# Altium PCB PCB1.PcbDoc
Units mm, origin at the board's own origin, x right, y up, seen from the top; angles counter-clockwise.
Board outline 66.23 x 50.49 mm, 2 copper layers (Top Layer, Bottom Layer); 33 components, 24 nets, 102 pads, 82 vias.
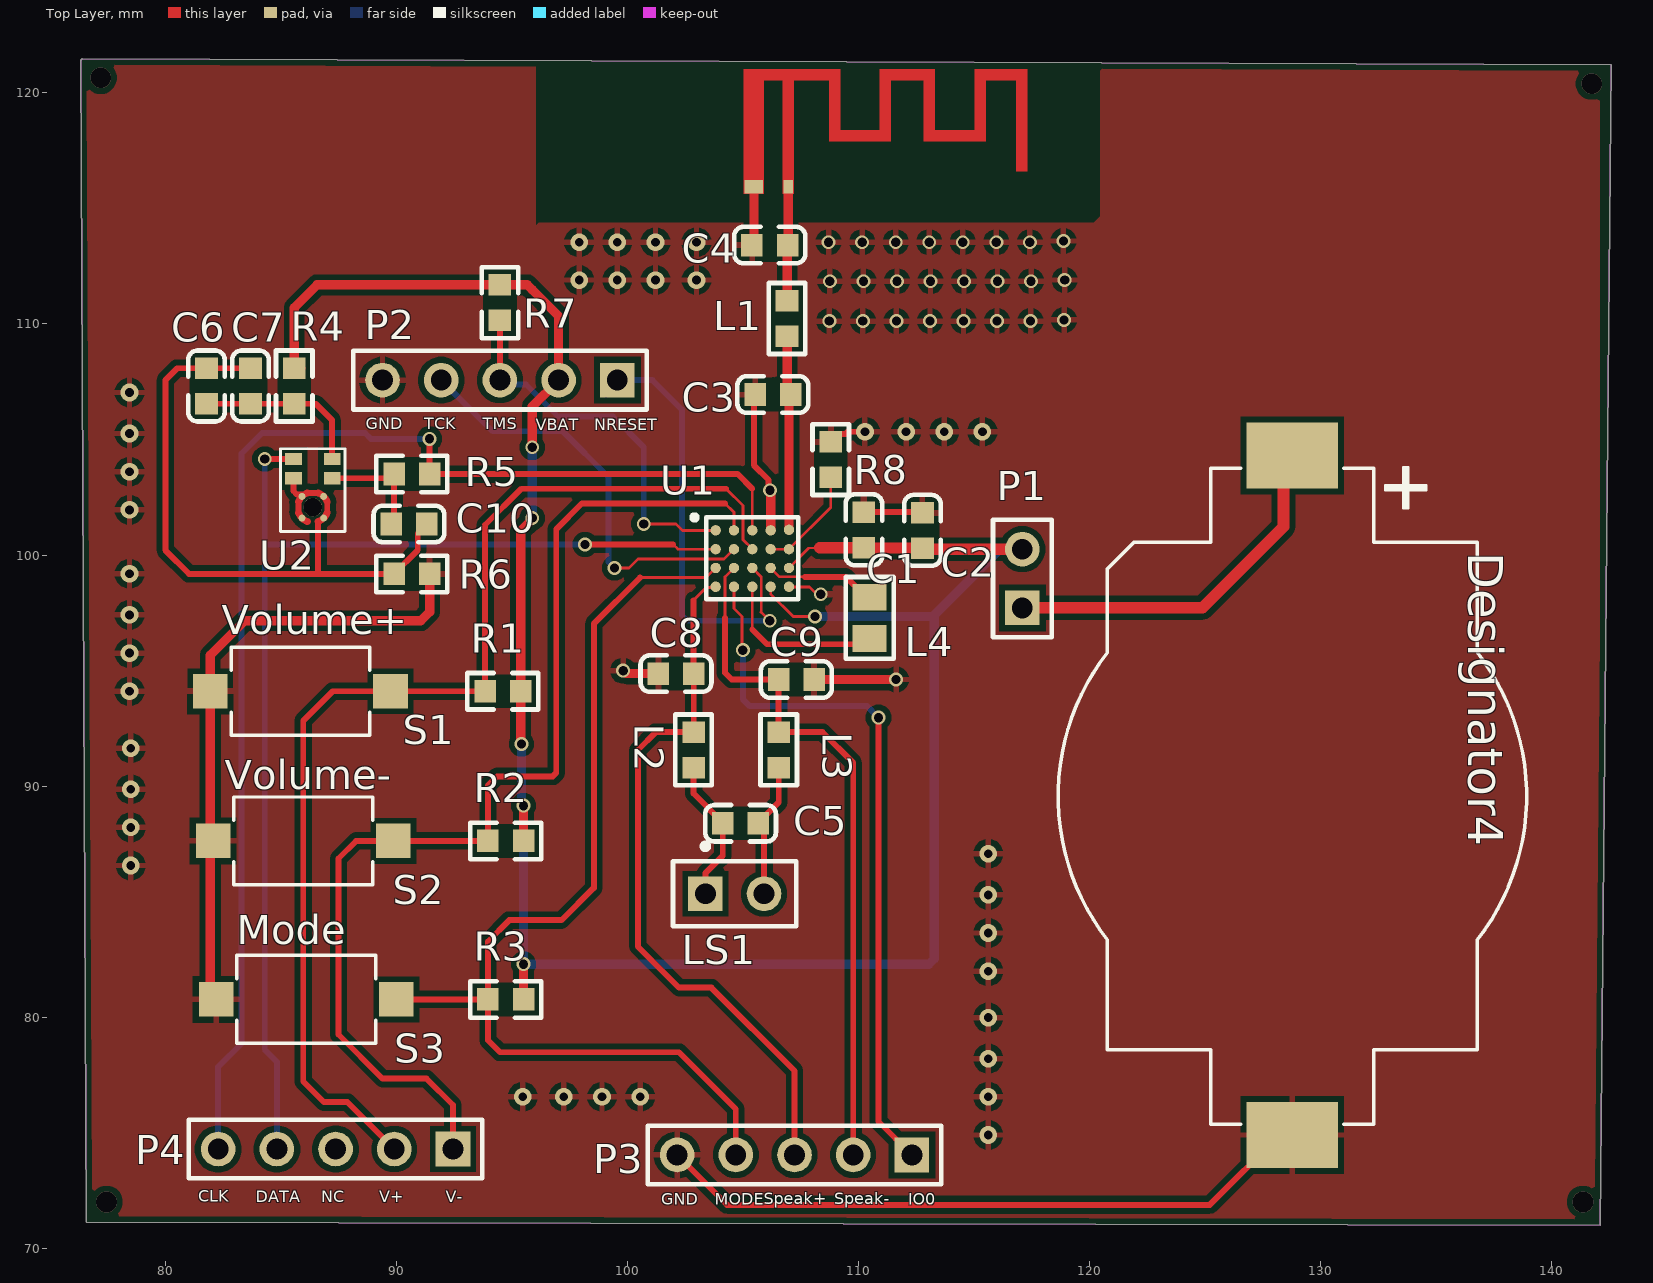
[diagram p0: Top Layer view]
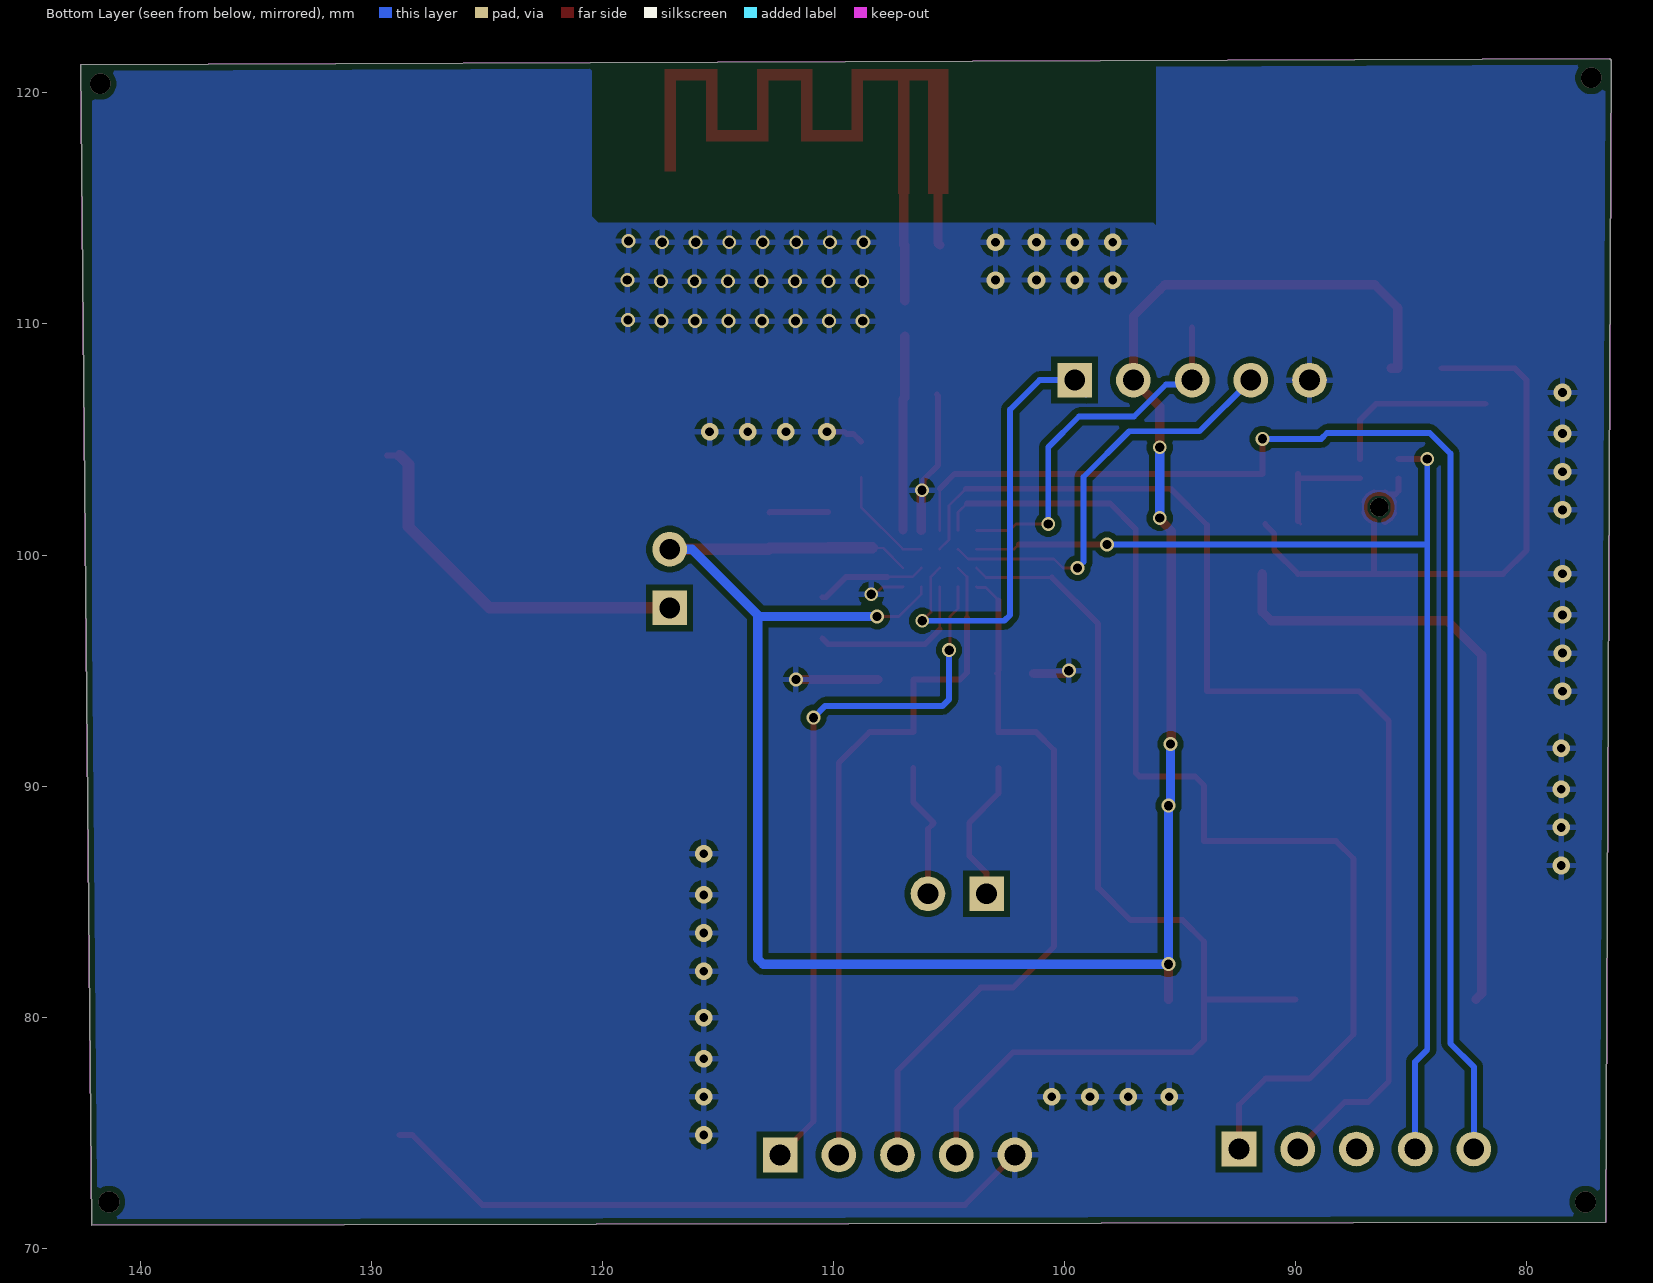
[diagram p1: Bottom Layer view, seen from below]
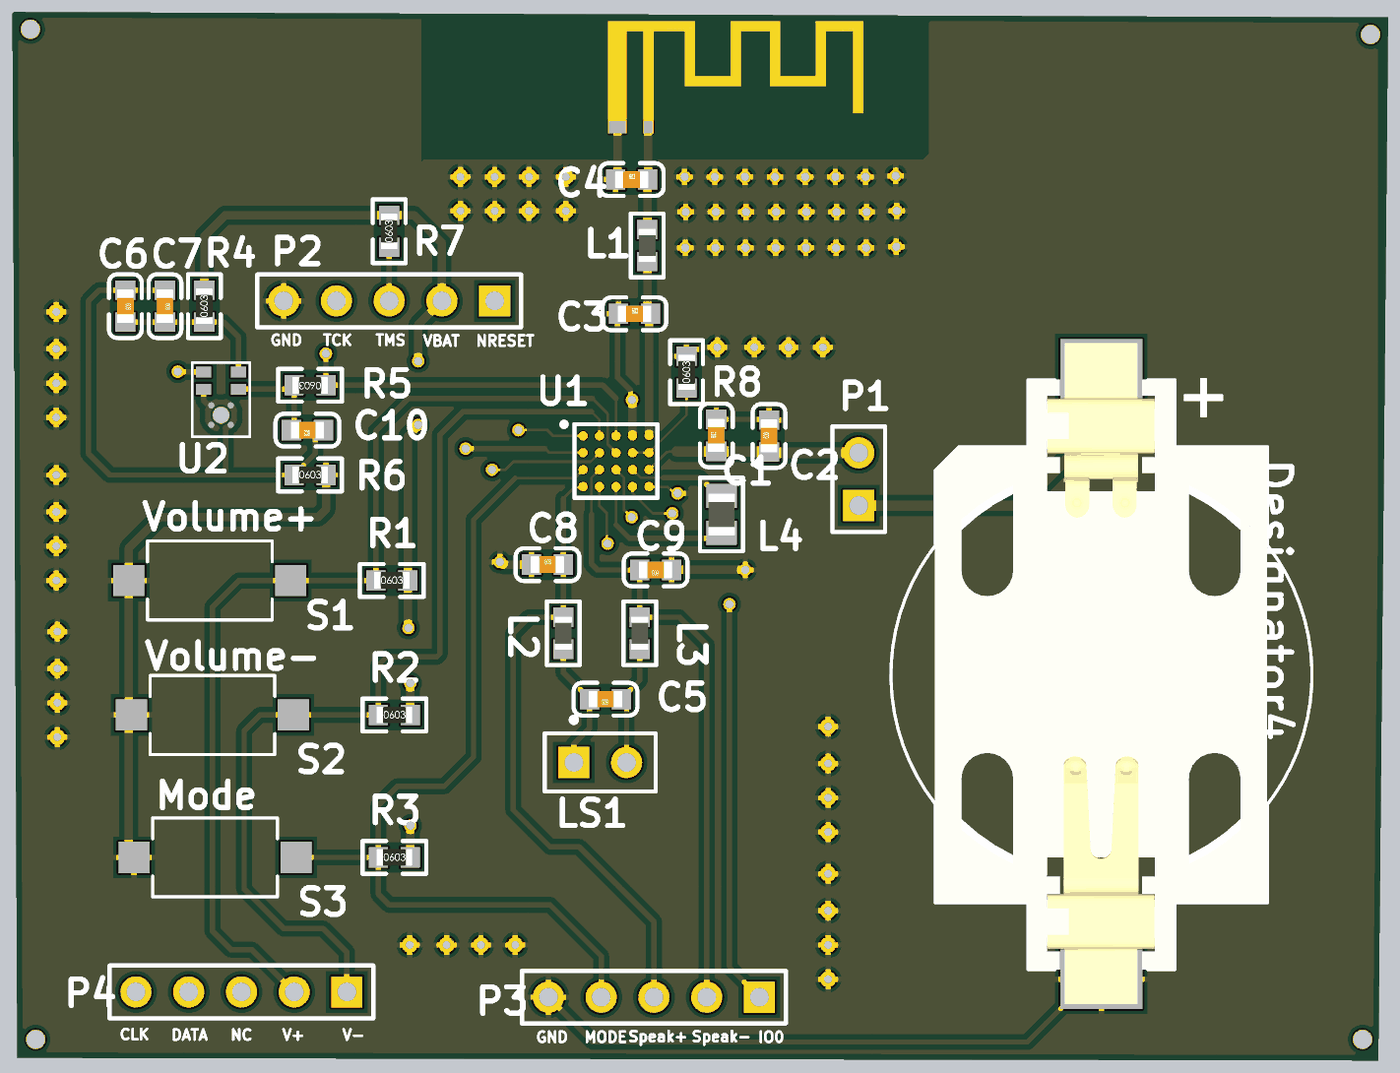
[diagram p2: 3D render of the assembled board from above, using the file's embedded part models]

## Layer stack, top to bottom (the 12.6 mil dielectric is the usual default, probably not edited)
Top Solder: solder mask 0.0102, Solder Resist, Dk 3.5
Top Layer: signal copper 0.0356
Dielectric 1: dielectric 0.32, FR-4, Dk 4.8
Bottom Layer: signal copper 0.0356
Bottom Solder: solder mask 0.0102, Solder Resist, Dk 3.5

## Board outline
76.581,71.12 76.347,121.412 76.414,121.478 142.581,121.217 142.113,70.993

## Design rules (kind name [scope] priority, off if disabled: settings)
Clearance [All] p1: gap=0.254 ignorepadtopadclearanceinfootprint=FALSE except(0: Arc-Hole Track-Hole SMDPad-Hole THPad-Hole Via-Hole Fill-Hole Poly-Hole Region-Hole Text-Hole; 0.1: Arc-SMDPad Track-SMDPad SMDPad-SMDPad)
PolygonConnect [All] p1: connectstyle=Relief reliefconductorwidth=0.254 reliefentries=4 polygonreliefangle="90 Angle" airgapwidth=0.254
RoutingVias [All] p1: holewidth=0.711 width=1.27 viastyle="Through Hole" minholewidth=0.711 minwidth=1.27 maxholewidth=0.711 maxwidth=1.27
SolderMaskExpansion [All] p1: expansion=0.102 istentingtop=FALSE
Width [All] p1: maxlimit=0.5 minlimit=0.1 preferedwidth=0.254
30 further rules are at their usual default settings.

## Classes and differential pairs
component class Sheet1: C1 C2 C3 C4 C5 C6 C7 C8 C9 C10 L1 L2 L3 L4 LS1 P1 P2 P3 P4 R1 R2 R3 R4 R5 R6 R7 S1 S2 S3 U1 U2

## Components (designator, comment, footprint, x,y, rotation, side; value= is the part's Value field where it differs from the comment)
C1 "Cap" 0603_C 110.236,101.092 r90 top value=1uF
C2 "Cap" 0603_C 112.776,101.067 r90 top value=10uF
C3 "Cap" 0603_C 106.299,106.946 r0 top value="1.5pF/2% 0603"
C4 "Cap" 0603_C 106.164,113.411 r0 top value="1.5pF/2% 0603"
C5 "Cap" 0603_C 104.902,88.392 r180 top value=15pF
C6 "Cap" 0603_C 81.788,107.315 r270 top value=10uF/10V
C7 "Cap" 0603_C 83.693,107.315 r270 top value=0.1uF/10V
C8 "Cap" 0603_C 102.108,94.869 r0 top value=15pF
C9 "Cap" 0603_C 107.315,94.615 r180 top value=15pF
C10 "Cap" 0603_C 90.551,101.346 r180 top value=0.1uF/10V
Designator4 "Comment" B-COINCELL-KEYSTONE-1060 128.778,89.535 r270 top
L1 "Inductor" 0603_L 106.909,110.236 r90 top value="3nH/10% 0603"
L2 "Inductor" 0603_L 102.87,91.567 r270 top value=15nH
L3 "Inductor" 0603_L 106.553,91.567 r270 top value=15nH
L4 "CKP2012N_2R2 0805" 0805_L 110.49,97.282 r270 top value=2.2uH
LS1 "Speaker" PIN2 103.378,85.344 r0 top
P1 "1.8V外部电源" HDR1X2 117.094,97.714 r90 top
P2 "JTAG" HDR1X5 99.568,107.569 r180 top
P3 "JTAG" HDR1X5 112.316,74.041 r180 top
P4 "JTAG" HDR1X5 92.456,74.295 r180 top
R1 "Res1" 0603_R 94.615,94.107 r0 top value=100K
R2 "Res1" 0603_R 94.742,87.63 r0 top value=100K
R3 "Res1" 0603_R 94.742,80.772 r0 top value=100K
R4 "Res1" 0603_R 85.59,107.315 r90 top value=22R
R5 "Res1" 0603_R 90.678,103.505 r180 top value=22R
R6 "Res1" 0603_R 90.678,99.187 r0 top value=22R
R7 "Res1" 0603_R 94.488,110.922 r90 top value=100K
R8 "Res1" 0603_R 108.805,104.131 r90 top value=100K (schematic designator R7)
S1 "Volume+" "S-C&K-RS-282G05A3-SM RT" 85.852,94.107 r0 top
S2 "Volume-" "S-C&K-RS-282G05A3-SM RT" 85.979,87.63 r0 top
S3 "Mode" "S-C&K-RS-282G05A3-SM RT" 86.106,80.772 r0 top
U1 "J10 SIP" JIP 106.845,98.984 r0 top
U2 "Digital Mic" SPH0641LM4H 86.448,102.06 r0 top

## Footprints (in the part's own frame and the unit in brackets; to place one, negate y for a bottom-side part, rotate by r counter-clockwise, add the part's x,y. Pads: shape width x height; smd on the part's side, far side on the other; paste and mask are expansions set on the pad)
0603_C [mm]
  rect 0.93x0.98 smd: 1(-0.77,0) 2(0.77,0)
  silkscreen extent -1.53,-0.79 1.54,0.79, body extent -0.8,-0.4 0.8,0.4, height 0.3
0603_L [mm]
  rect 0.93x0.98 smd: 1(-0.77,0) 2(0.77,0)
  silkscreen extent -1.53,-0.79 1.54,0.79, body extent -0.82,-0.41 0.83,0.41, height 0.46
0603_R [mm]
  rect 0.93x0.98 smd: 1(-0.77,0) 2(0.77,0)
  silkscreen extent -1.53,-0.79 1.54,0.79, body extent -0.85,-0.4 0.85,0.4, height 0.56
0805_L [mm]
  rect 1.16x1.47 smd: 1(-0.89,0) 2(0.89,0)
  silkscreen extent -1.77,-1.04 1.77,1.03, body extent -1.02,-0.64 1.03,0.64, height 0.6
B-COINCELL-KEYSTONE-1060 [mm] "Coincell Battery Holder,20mm Diameter, 2-Leads, Body Dia 23.0mm (max), Pitch 29.4mm, IPC Medium Density"
  rect 2.85x3.95 smd: 1(-14.77,0) 2(14.63,0)
  silkscreen extent -14.28,-10.13 14.17,10.13, body extent -15.99,-8.02 15.83,7.98, height 5.67
HDR1X2 [mm] "Connector; Header; 2 Position"
  rect 1.5x1.5 hole 0.9: 1(0,0)
  round 1.5 hole 0.9: 2(2.54,0)
  silkscreen extent -1.27,-1.27 3.81,1.27
HDR1X5 [mm] "Connector; Header; 5 Position"
  rect 1.5x1.5 hole 0.9: 1(0,0)
  round 1.5 hole 0.9: 2(2.54,0) 3(5.08,0) 4(7.62,0) 5(10.16,0)
  silkscreen extent -1.27,-1.27 11.43,1.27
JIP [mm]
  round 0.45 smd paste-10 mask+0.05: 1(-3.023,2.083) 2(-2.229,2.083) 3(-1.435,2.083) 4(-0.641,2.083) 5(0.152,2.108) 6(-3.023,1.27) 7(-2.229,1.27) 8(-1.435,1.27) 9(-0.641,1.27) 10(0.152,1.27) 11(-3.023,0.457) 12(-2.229,0.457) 13(-1.435,0.457) 14(-0.641,0.457) 15(0.152,0.457) 16(-3.023,-0.356) 17(-2.229,-0.356) 18(-1.435,-0.356) 19(-0.641,-0.356) 20(0.152,-0.356)
  silkscreen extent -4.04,-0.9 0.56,2.74, body extent -3.33,-0.79 0.43,2.53, height 0.58
PIN2 [mm] "Photosensitive Diode; 2 Leads"
  rect 1.5x1.5 hole 0.9: 1(0,0)
  round 1.5 hole 0.9: 2(2.54,0)
  silkscreen extent -1.4,-1.4 3.94,2.17
"S-C&K-RS-282G05A3-SM RT" [mm] "RS-282G05A3-SM RT,2-Leads, Body 6 x 3.6 mm (max), Pitch 7.8 mm, IPC Medium Density"
  rect 1.5x1.5 smd: 1(-3.9,0) 2(3.9,0)
  silkscreen extent -3,-1.9 3,1.9
SPH0641LM4H [mm]
  rect 0.725x0.522 smd mask+0.102: 1(-0.893,2.088) 5(0.781,2.088)
  rect 0.725x0.522 smd paste+0 mask+0.102: 2(-0.895,1.261) 4(0.781,1.261)
  round 0.3 smd paste+0 mask+0: 3(-0.524,-0.46) 3(-0.524,0.476) 3(0.412,-0.46) 3(0.412,0.476)
  round 0.8 hole 0.8 mask+0: ""(-0.056,0.008)
  Top Layer lines w0.3: -0.679,-0.219 ccw(c-0.056,0.008) -0.283,-0.615 ; -0.679,0.234 cw(c-0.056,0.008) -0.283,0.631 ; 0.17,-0.615 ccw(c-0.056,0.008) 0.567,-0.219 ; 0.17,0.631 cw(c-0.056,0.008) 0.567,0.234
  silkscreen extent -1.45,-1.04 1.34,2.54

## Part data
C1 C2 C3 C4 C5 C6 C7 C8 C9 C10: "Capacitor"
L4: library part Inductor, "Inductor"
LS1: "Loudspeaker"
P1: library part "Header 2", "Header, 2-Pin"
P2 P3 P4: library part "Header 5", "Header, 5-Pin"
R1 R2 R3 R4 R5 R6 R7 R8: "Resistor"
S1 S2 S3: library part SW-PB, "Switch"
U1 U2: library part Component_1

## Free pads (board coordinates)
  rect 0.4x0.6 smd: 1(106.961,115.936)
  rect 0.8x0.6 smd: 2(105.478,115.936)

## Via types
v1: diameter 0.6, hole 0.4, Top Layer to Bottom Layer, 42 vias
v2: diameter 0.762, hole 0.381, Top Layer to Bottom Layer, 36 vias
v3: diameter 0.9, hole 0.9, Top Layer to Bottom Layer, 4 vias

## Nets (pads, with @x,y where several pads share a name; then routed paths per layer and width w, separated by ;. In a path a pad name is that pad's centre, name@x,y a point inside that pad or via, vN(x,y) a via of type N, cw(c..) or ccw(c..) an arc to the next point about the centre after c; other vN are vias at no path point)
AGND: R8.1 U1.9 U1.10 | length 4.6
  Top Layer w0.12: U1.9 U1.10 108.805,102.062 R8.1
ANT: C3.2 L1.1 U1.5 | length 8.4
  Top Layer w0.4: L1.1 106.921,109.453 106.921,106.82 106.998,106.743 U1.5
BAT1: Designator4.1 P1.1 | length 16.5
  Top Layer w0.254: Designator4.1 Designator4.1@129.328,104.305
  Top Layer w0.5: P1.1 124.892,97.714 128.397,101.219 128.397,103.924 Designator4.1
GND: C1.2 C2.2 C3.1 C4.1 C8.1 C9.1 Designator4.2 P2.5 P3.5 pad.2 R6.2 R8.2 S1.1 S2.1 S3.1 U1.4 U1.20 | length 74.6
  Top Layer w0.12: U1.20 107.011,98.615 107.887,98.615 108.077,98.425
  Top Layer w0.254: P3.5 104.315,71.882 125.205,71.882 128.228,74.905 Designator4.2 ; C3.1 105.478,106.895 105.478,103.889 106.113,103.253 106.113,102.872 v1(106.179,102.806) ; R8.2 109.143,105.239 109.43,105.239 109.525,105.334 v2(110.287,105.334) ; C1.2 112.751,101.862 C2.2
  Top Layer w0.4: S3.1 81.952,81.026 S1.1 81.952,95.66 83.447,97.155 91.063,97.155 91.448,97.54 R6.2 ; v1@99.949,94.869 C8.1 ; C4.1 105.478,113.495 pad.2 ; U1.4 v1@106.204,102.691 ; C9.1 v1(111.633,94.615)
  other v1: 99.822,94.996 108.373,98.302 108.743,110.123 110.194,110.123 111.645,110.123 113.097,110.123 114.548,110.123 116,110.123 117.451,110.123 118.903,110.174 108.766,111.849 110.217,111.849 111.668,111.849 113.12,111.849 114.571,111.849 116.023,111.849 117.474,111.849 118.926,111.9 108.712,113.538 110.163,113.538 111.615,113.538 113.066,113.538 114.518,113.538 115.969,113.538 117.421,113.538 118.872,113.589
  other v2: 115.621,74.905 95.476,76.556 97.254,76.556 98.905,76.556 100.556,76.556 115.621,76.556 115.621,78.207 115.621,79.985 115.621,81.991 115.621,83.642 115.621,85.293 78.511,86.563 115.621,87.071 78.511,88.214 78.511,89.865 78.511,91.643 78.461,94.107 78.461,95.758 78.461,97.409 78.461,99.187 78.461,101.956 78.461,103.607 78.461,105.258 112.065,105.334 113.716,105.334 115.367,105.334 78.461,107.036 97.917,111.9 99.568,111.9 101.219,111.9 102.997,111.9 97.917,113.538 99.568,113.538 101.219,113.538 102.997,113.538
IO0: P3.1 U1.17 | length 31.2
  Top Layer w0.12: U1.17 104.616,97.695 104.969,97.342 104.969,95.917 v1(105.001,95.885)
  Top Layer w0.254: v1(110.871,92.964) 110.871,75.486 P3.1
  Bottom Layer w0.254: v1(105.001,95.885) 105.001,93.754 105.283,93.472 110.363,93.472 v1(110.871,92.964) ; P3.1@112.014,74.343 P3.1
MIC_CLK: P4.5 R5.1 U1.3 | length 56.7
  Top Layer w0.12: U1.3 105.41,102.87
  Top Layer w0.254: v1(91.44,105.029) 91.44,103.513 R5.1 104.775,103.505 105.41,102.87
  Bottom Layer w0.254: P4.5 82.296,77.851 83.312,78.867 83.312,104.394 84.201,105.283 88.646,105.283 88.9,105.029 v1(91.44,105.029)
MIC_DATA: P4.4 U1.6 U2.1 | length 51
  Top Layer w0.12: 101.981,100.461 102.189,100.254 U1.6
  Top Layer w0.254: v1@84.202,104.148 U2.1 ; v1@98.175,100.461 101.981,100.461
  Bottom Layer w0.254: v1(84.312,104.161) 84.312,100.457 ; P4.4 84.836,78.073 84.312,78.597 84.312,100.457 ; v1(98.171,100.457) 84.312,100.457
Mode: P3.4 R3.1 S3.2 U1.11 | length 45.4
  Top Layer w0.12: 100.556,99.032 103.414,99.032 U1.11
  Top Layer w0.254: S3.2 R3.1 ; 100.556,99.032 98.552,97.028 98.552,85.598 97.155,84.201 94.894,84.201 93.972,83.28 R3.1 ; P3.4 104.696,76.025 102.235,78.486 94.488,78.486 93.972,79.002 R3.1
NetA1_1: C4.2 L1.2 pad.1 | length 5
  Top Layer w0.4: L1.2 106.921,111.019 106.921,113.398 C4.2 106.961,113.438 pad.1
NetC5_1: C5.1 L3.2 LS1.2 | length 5.9
  Top Layer w0.254: LS1.2 105.918,88.146 C5.1 105.672,88.417 106.553,89.298 L3.2
NetC5_2: C5.2 L2.2 LS1.1 | length 6.3
  Top Layer w0.254: L2.2 102.87,89.679 104.132,88.417 C5.2 104.132,86.987 103.378,86.233 LS1.1
NetC6_1: C6.1 C7.1 C10.1 R6.1 U2.2 U2.3 | length 28.8
  Top Layer w0.254: C7.1 C6.1 80.526,108.085 80.01,107.569 80.01,100.211 81.034,99.187 86.614,99.187 ; U2.2 85.554,102.769 85.703,102.62 U2.3@85.924,102.62 ; 85.769,101.841 85.769,102.295 ; 86.165,102.691 86.619,102.691 ; 86.619,101.445 86.619,99.192 86.614,99.187 ; 87.015,101.841 87.015,102.295 ; R6.1@89.773,99.187 86.614,99.187 ; R6.1 90.932,100.211 90.932,100.932 91.321,101.321 C10.1
NetC6_2: C6.2 C7.2 R4.1 U2.5 | length 7.4
  Top Layer w0.254: C6.2 C7.2 R4.1 86.519,106.545 87.229,105.834 U2.5
NetC10_2: C10.2 R5.2 U2.4 | length 5
  Top Layer w0.12: R5.2@89.725,103.322 R5.2 ; C10.2 C10.2@89.908,101.473
  Top Layer w0.254: U2.4 R5.2@89.725,103.322 ; C10.2@89.908,101.473 R5.2
NetL4_1: L4.1 U1.14 | length 4.8
  Top Layer w0.12: U1.14 106.589,99.056 107.696,99.056
  Top Layer w0.254: 107.696,99.056 109.451,99.056 110.335,98.172 L4.1
NetL4_2: L4.2 U1.18 | length 7.3
  Top Layer w0.12: 105.41,96.774 U1.18
  Top Layer w0.254: 105.41,96.774 106.045,96.139 110.236,96.139 L4.2
NRESET: P2.1 U1.13 | length 19.6
  Top Layer w0.12: U1.13 105.795,99.056 105.795,97.54 105.791,97.536 105.791,97.528 v1(106.164,97.155)
  Bottom Layer w0.254: P2.1@99.072,106.946 P2.1@99.695,107.569 ; P2.1 P2.1@99.695,107.569 ; v1(106.164,97.155) 102.616,97.155 102.362,97.409 102.362,106.299 101.092,107.569 P2.1@99.695,107.569
Speaker+: C8.2 L2.1 P3.3 U1.16 | length 30.8
  Top Layer w0.12: C8.2@102.87,95.004 C8.2@103.005,94.869 ; 102.87,98.044 103.417,98.591 103.786,98.591 U1.16
  Top Layer w0.254: C8.2@102.87,95.004 102.87,98.044 ; C8.2 102.878,92.345 L2.1 101.231,92.337 100.461,91.567 100.461,83.054 102.235,81.28 103.636,81.28 107.236,77.68 P3.3
Speaker-: C9.2 L3.1 P3.2 U1.12 | length 30.2
  Top Layer w0.12: 104.231,97.282 104.231,99.056 U1.12
  Top Layer w0.254: 104.231,97.282 104.231,94.905 104.521,94.615 C9.2 106.545,92.345 L3.1 108.45,92.337 109.776,91.011 P3.2
TCK: P2.4 U1.7 | length 18.5
  Top Layer w0.12: v1(99.441,99.441) 100.076,99.441 100.461,99.826 104.188,99.826 U1.7
  Bottom Layer w0.254: P2.4 94.163,105.354 97.211,105.354 99.187,103.378 99.187,99.695 v1(99.441,99.441)
TMS: P2.3 R7.1 U1.1 | length 16.2
  Top Layer w0.12: v1(100.711,101.346) 102.108,101.346 102.387,101.067 U1.1
  Top Layer w0.254: P2.3 R7.1@94.488,109.846
  Bottom Layer w0.254: P2.3 94.678,107.379 95.619,107.379 97,105.997 99.378,105.997 100.711,104.664 v1(100.711,101.346)
VBAT: C1.1 C2.1 P1.2 P2.2 R1.2 R2.2 R3.2 R4.2 R7.2 U1.15 U1.19 | length 103.1
  Top Layer w0.12: U1.19 106.204,98.317 107.183,97.338 v1(108.12,97.338) ; U1.15 107.853,100.297 108.331,100.322
  Top Layer w0.254: P2.2@97.112,107.612 P2.2@97.155,107.569 ; C2.1 C2.1@112.819,100.254
  Top Layer w0.4: R4.2@85.879,108.085 R4.2 85.59,110.704 86.578,111.692 R7.2 95.674,111.692 95.884,111.481 97.028,110.338 P2.2 95.885,106.426 v1(95.885,104.664) ; v1(95.417,91.821) 95.385,91.853 R1.2 95.385,101.046 95.885,101.546 v1(95.885,101.6) ; v1(95.504,89.154) 95.508,89.15 95.508,87.634 R2.2 ; R3.2 v1(95.512,82.296)
  Top Layer w0.5: 108.331,100.322 110.236,100.311 C2.1 ; C2.1@112.819,100.254 P1.2
  Bottom Layer w0.4: v1(95.417,91.821) 95.417,89.295 95.504,89.208 v1(95.504,89.154) 95.508,89.15 95.508,82.3 v1(95.512,82.296) 113.05,82.296 113.284,82.53 113.284,97.338 v1(108.12,97.338) ; v1(95.885,101.6) v1(95.885,104.664) ; 113.284,97.409 116.129,100.254 P1.2
Volume+: P4.2 R1.1 S1.2 U1.8 | length 50.5
  Top Layer w0.12: 104.267,102.87 105.001,102.136 105.001,100.663 U1.8
  Top Layer w0.254: P4.2 87.884,76.327 86.868,76.327 85.979,77.216 85.979,92.832 87.254,94.107 S1.2 R1.1 93.845,101.298 95.417,102.87 104.267,102.87
Volume-: P4.1 R2.1 S2.2 U1.2 | length 47.7
  Top Layer w0.12: 104.231,102.235 104.616,101.85 U1.2
  Top Layer w0.254: P4.1 92.456,76.2 91.313,77.343 89.408,77.343 87.503,79.248 87.503,86.868 88.265,87.63 S2.2 R2.1 93.972,90.035 94.361,90.424 96.777,90.424 96.926,90.573 96.926,101.117 98.044,102.235 104.231,102.235
pads on no net: P4.3 U2.
copper on no net:
  other v3: 77.47,72.009 141.351,72.009 141.732,120.396 77.216,120.65

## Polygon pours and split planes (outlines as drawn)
GND on Top Layer "NONET_L01_P-001" (solid, pour order 0): 76.302,121.539 76.403,121.437 96.037,121.437 96.037,114.249 96.164,114.376 120.193,114.376 120.472,114.656 120.472,121.26 142.545,121.26 142.088,120.802 142.088,70.968 76.632,70.968 76.302,71.298 76.302,121.488
GND on Bottom Layer "NONET_L01_P-001" (solid, pour order 2): 76.302,121.539 76.403,121.437 96.037,121.437 96.037,114.249 96.164,114.376 120.193,114.376 120.472,114.656 120.472,121.26 142.545,121.26 142.088,120.802 142.088,70.968 76.632,70.968 76.302,71.298 76.302,121.488

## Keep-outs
Keep-Out Layer:
  the board outline again, w0.01

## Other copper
Top Layer:
  rectangle: 105.021,115.631 105.921,120.736
  rectangle: 106.721,115.631 107.221,120.762
  rectangle: 105.021,120.531 109.221,121.031
  rectangle: 108.721,117.891 109.221,120.711
  rectangle: 108.811,117.891 111.351,118.386
  rectangle: 110.921,117.891 111.421,120.711
  rectangle: 110.921,120.531 113.321,121.031
  rectangle: 112.821,117.891 113.321,120.711
  rectangle: 112.836,117.891 115.325,118.391
  rectangle: 115.021,117.891 115.521,120.711
  rectangle: 115.021,120.531 117.321,121.031
  rectangle: 116.821,116.591 117.321,120.711

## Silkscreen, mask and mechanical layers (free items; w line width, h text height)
Top Overlay:
  text "GND" at 88.677,105.439 h0.5
  text "TCK" at 91.22,105.439 h0.5
  text "TMS" at 93.749,105.439 h0.5
  text "VBAT" at 96.035,105.408 h0.5
  text "NRESET" at 98.575,105.408 h0.5
  text "CLK" at 81.424,72.011 h0.5
  text "DATA" at 83.913,71.985 h0.5
  text "NC" at 86.764,71.985 h0.5
  text "V+" at 89.256,71.985 h0.5
  text "V-" at 92.149,71.985 h0.5
  text "Speak+" at 105.913,71.911 h0.5
  text "Speak-" at 108.963,71.911 h0.5
  text "GND" at 101.471,71.88 h0.5
  text "MODE" at 103.793,71.88 h0.5
  text "IO0" at 112.164,71.88 h0.5
Top Solder:
  rectangle: 105.021,115.639 105.921,120.745
  rectangle: 106.721,115.639 107.221,120.77
  rectangle: 105.021,120.539 109.221,121.039
  rectangle: 108.721,117.899 109.221,120.719
  rectangle: 108.811,117.899 111.351,118.394
  rectangle: 110.921,117.899 111.421,120.719
  rectangle: 110.921,120.539 113.321,121.039
  rectangle: 112.821,117.899 113.321,120.719
  rectangle: 112.836,117.899 115.325,118.399
  rectangle: 115.021,117.899 115.521,120.719
  rectangle: 115.021,120.539 117.321,121.039
  rectangle: 116.821,116.599 117.321,120.719
Mechanical 1:
  the board outline again, w0.01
